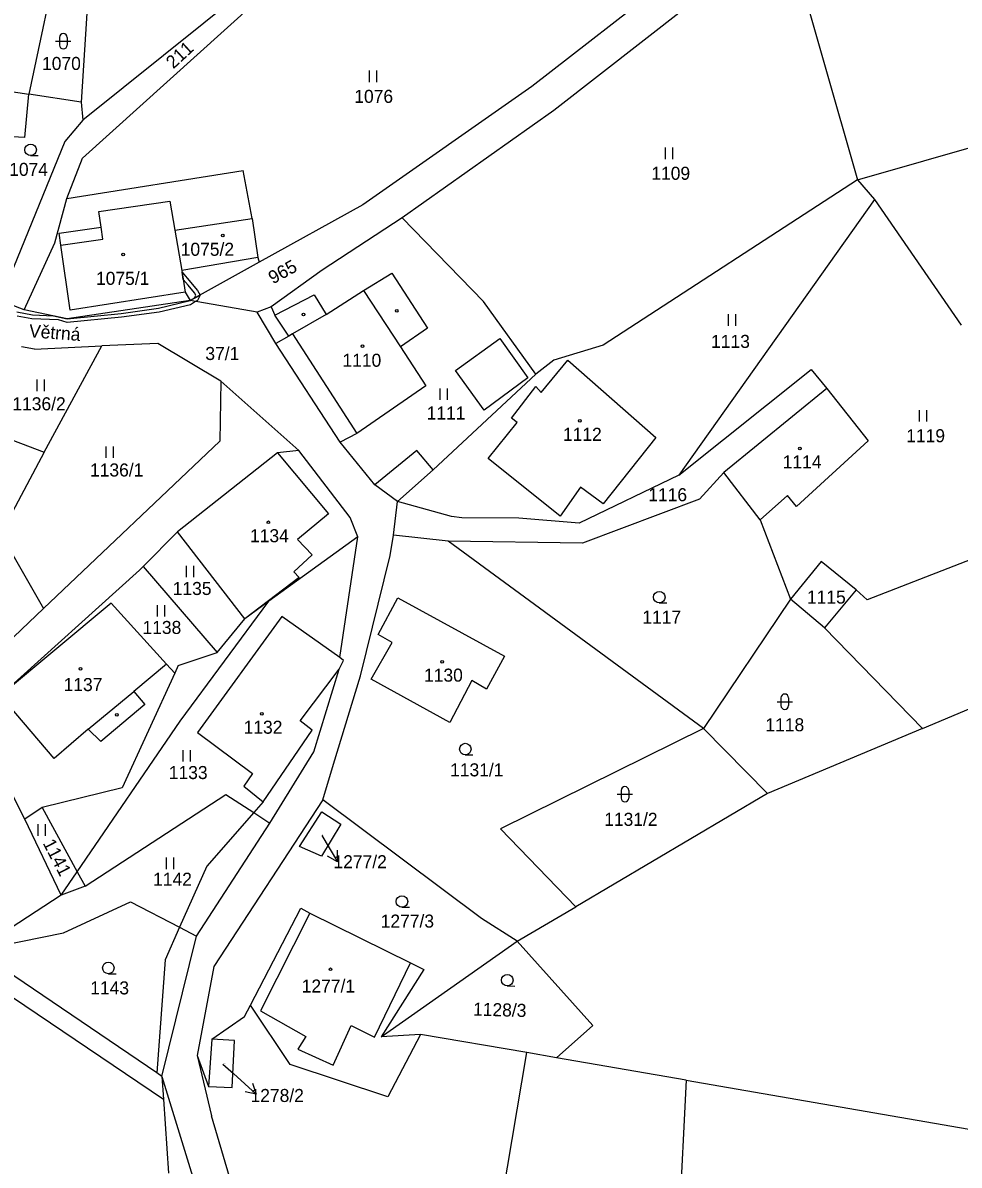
# Model space of a CAD drawing. Extents: x -670359 to -668019, y -978807 to -976674.
# Drawn here: x -670104.9 to -669982.9, y -977860.3 to -977711.4 of the extents above; entities that cross this region are included whole.
import ezdxf

# ---------------------------------------------------------------- set-up
doc = ezdxf.new("R2010")
doc.units = 0
for name, color, linetype in [('Hranice parcel', 7, 'Continuous'), ('Parcelní čísla', 7, 'Continuous'), ('Pop  PČ popisy', 7, 'Continuous'), ('Vnitřní kresba', 7, 'Continuous'), ('Věcná břemena k části', 7, 'Continuous'), ('Značky budov', 7, 'Continuous'), ('Značky kultur', 7, 'Continuous')]:
    doc.layers.add(name, color=color, linetype=linetype)

msp = doc.modelspace()

# ---------------------------------------------------------------- linework, layer by layer
at = {"layer": 'Hranice parcel'}
for p, q in [((-670075.04, -977736.87), (-670076.2, -977730.61)), ((-670085.1, -977738.43), (-670075.04, -977736.87)), ((-670075.04, -977736.87), (-670074.28, -977741.98)), ((-670085.1, -977738.43), (-670084.21, -977743.67)), ((-670084.21, -977743.67), (-670083.75, -977746.5)), ((-670083.75, -977746.5), (-670083.13, -977747.6)), ((-670040.51, -977831.14), (-670030.66, -977842.12)), ((-670030.66, -977842.12), (-670035.36, -977846.32)), ((-670035.36, -977846.32), (-670039.24, -977845.65)), ((-670018.5, -977849.23), (-670035.36, -977846.32))]:
    msp.add_line(p, q, dxfattribs=at)
for points in [[(-670100, -977701.17), (-670104.16, -977720.69)], [(-670096, -977701.2), (-670097.32, -977721.73)], [(-670005.01, -977700.79), (-669996.13, -977731.83)], [(-670097.16, -977729.02), (-670067.28, -977702.04)], [(-670020.57, -977705.64), (-670038.59, -977719.67)], [(-670076.09, -977707.16), (-670097.12, -977724.06)], [(-670018.27, -977709.18), (-670035.74, -977722.81)], [(-670038.59, -977719.67), (-670060.63, -977735.12)], [(-669996.13, -977731.83), (-669953.55, -977719.62)], [(-670109.04, -977719.94), (-670104.16, -977720.69)], [(-670097.32, -977721.73), (-670104.16, -977720.69)], [(-670097.32, -977721.73), (-670097.12, -977724.06)], [(-670097.12, -977724.06), (-670099.46, -977726.85)], [(-670035.74, -977722.81), (-670055.47, -977736.78)], [(-670099.46, -977726.85), (-670106.63, -977744.47)], [(-670099.2, -977734.29), (-670097.16, -977729.02)], [(-670099.2, -977734.29), (-670076.2, -977730.61)], [(-669996.13, -977731.83), (-670029.31, -977753.41)], [(-669996.13, -977731.83), (-669993.93, -977734.4)], [(-670100.76, -977740.04), (-670099.2, -977734.29)], [(-669993.93, -977734.4), (-670019.43, -977770.35)], [(-669993.93, -977734.4), (-669982.65, -977750.8)], [(-670060.63, -977735.12), (-670074.12, -977742.6)], [(-670055.47, -977736.78), (-670065.91, -977743.63)], [(-670044.91, -977747.7), (-670055.47, -977736.78)], [(-670104.74, -977748.8), (-670100.76, -977740.04)], [(-670074.28, -977741.98), (-670074.12, -977742.6)], [(-670074.12, -977742.6), (-670083.13, -977747.6)], [(-670065.91, -977743.63), (-670072.58, -977748.39)], [(-670060.55, -977746.28), (-670056.85, -977744.02)], [(-670056.85, -977744.02), (-670052.18, -977751.17)], [(-670065.38, -977749.4), (-670060.55, -977746.28)], [(-670104.74, -977748.8), (-670109.17, -977747.09)], [(-670083.13, -977747.6), (-670099.15, -977749.96)], [(-670074.4, -977749.12), (-670083.13, -977747.6)], [(-670072.1, -977749.51), (-670066.96, -977746.83)], [(-670066.96, -977746.83), (-670065.38, -977749.4)], [(-670038.06, -977757.19), (-670044.91, -977747.7)], [(-670099.15, -977749.96), (-670104.74, -977748.8)], [(-670072.58, -977748.39), (-670074.4, -977749.12)], [(-670071.96, -977753.19), (-670074.4, -977749.12)], [(-670072.58, -977748.39), (-670072.1, -977749.51)], [(-670052.18, -977751.17), (-670055.72, -977753.63)], [(-670103.42, -977753.93), (-670105.1, -977753.62)], [(-670103.42, -977753.93), (-670094.63, -977753.51)], [(-670102.16, -977767.34), (-670094.63, -977753.51)], [(-670087.33, -977753.17), (-670094.63, -977753.51)], [(-670079.12, -977758.1), (-670087.33, -977753.17)], [(-670063.57, -977766.05), (-670071.96, -977753.19)], [(-670055.72, -977753.63), (-670052.4, -977758.69)], [(-670029.31, -977753.41), (-670035.73, -977755.36)], [(-670035.73, -977755.36), (-670038.06, -977757.19)], [(-670037.36, -977759.59), (-670033.89, -977755.38)], [(-670033.89, -977755.38), (-670022.44, -977765.45)], [(-670019.43, -977770.35), (-670002.21, -977756.56)], [(-670002.21, -977756.56), (-670000.15, -977759.05)], [(-670079.12, -977758.1), (-670079.26, -977765.94)], [(-670068.94, -977767.13), (-670079.12, -977758.1)], [(-670038.06, -977757.19), (-670051.44, -977769.65)], [(-670052.4, -977758.69), (-670061.41, -977764.94)], [(-670041.23, -977762.92), (-670038.05, -977758.8)], [(-670038.05, -977758.8), (-670037.36, -977759.59)], [(-670000.15, -977759.05), (-670013.59, -977770)], [(-670000.15, -977759.05), (-669994.75, -977765.89)], [(-670044.3, -977768.18), (-670040.51, -977763.49)], [(-670040.51, -977763.49), (-670041.23, -977762.92)], [(-670108.36, -977764.99), (-670102.16, -977767.34)], [(-670061.41, -977764.94), (-670063.57, -977766.05)], [(-670022.44, -977765.45), (-670029.3, -977774.1)], [(-669994.75, -977765.89), (-670004.1, -977774.46)], [(-670102.16, -977767.34), (-670107.81, -977777.99)], [(-670079.26, -977765.94), (-670102.21, -977787.73)], [(-670068.94, -977767.13), (-670071.75, -977767.43)], [(-670062.28, -977775.89), (-670068.94, -977767.13)], [(-670059.05, -977771.6), (-670063.57, -977766.05)], [(-670071.75, -977767.43), (-670084.78, -977777.74)], [(-670034.92, -977775.7), (-670044.3, -977768.18)], [(-670051.44, -977769.65), (-670056.11, -977773.78)], [(-670019.43, -977770.35), (-670032.43, -977776.6)], [(-670013.59, -977770), (-670016.73, -977773.49)], [(-670008.83, -977776.19), (-670013.59, -977770)], [(-670056.11, -977773.78), (-670059.05, -977771.6)], [(-670032.25, -977771.9), (-670034.92, -977775.7)], [(-670029.3, -977774.1), (-670032.25, -977771.9)], [(-670005.29, -977773.01), (-670008.83, -977776.19)], [(-670004.1, -977774.46), (-670005.29, -977773.01)], [(-670056.62, -977778.17), (-670056.11, -977773.78)], [(-670049.08, -977775.75), (-670056.11, -977773.78)], [(-670016.73, -977773.49), (-670031.98, -977779.22)], [(-670061.26, -977778.38), (-670062.28, -977775.89)], [(-670047.72, -977775.92), (-670049.08, -977775.75)], [(-670040.28, -977775.97), (-670047.72, -977775.92)], [(-670032.43, -977776.6), (-670040.28, -977775.97)], [(-670008.83, -977776.19), (-670004.9, -977786.53)], [(-669966.28, -977775.47), (-669994.9, -977786.6)], [(-670084.78, -977777.74), (-670089.23, -977782.26)], [(-670076, -977789.08), (-670084.78, -977777.74)], [(-670107.81, -977777.99), (-670102.21, -977787.73)], [(-670061.26, -977778.38), (-670072.85, -977786.78)], [(-670063.62, -977794.12), (-670061.26, -977778.38)], [(-670057.04, -977780.81), (-670056.62, -977778.17)], [(-670049.5, -977778.94), (-670056.62, -977778.17)], [(-670031.98, -977779.22), (-670049.5, -977778.94)], [(-670016.24, -977803.38), (-670049.5, -977778.94)], [(-670089.7, -977782.74), (-670089.23, -977782.26)], [(-670089.23, -977782.26), (-670079.61, -977793.47)], [(-670060.91, -977796.54), (-670057.04, -977780.81)], [(-670000.87, -977781.6), (-670004.9, -977786.53)], [(-669996.33, -977785.31), (-670000.87, -977781.6)], [(-670089.7, -977782.74), (-670107.82, -977799.09)], [(-669987.66, -977803.37), (-669944.4, -977785.17)], [(-670058.63, -977791.12), (-670056.07, -977786.35)], [(-670056.07, -977786.35), (-670042.14, -977793.95)], [(-670004.9, -977786.53), (-670016.24, -977803.38)], [(-670000.45, -977790.24), (-670004.9, -977786.53)], [(-669996.33, -977785.31), (-670000.45, -977790.24)], [(-669994.9, -977786.6), (-669996.33, -977785.31)], [(-670114.79, -977799.68), (-670102.21, -977787.73)], [(-670093.41, -977787.03), (-670107.82, -977799.09)], [(-670086.19, -977795), (-670093.41, -977787.03)], [(-670072.85, -977786.78), (-670076, -977789.08)], [(-670071.18, -977788.79), (-670082.17, -977803.91)], [(-670079.61, -977793.47), (-670076, -977789.08)], [(-670063.62, -977794.12), (-670071.18, -977788.79)], [(-670056.8, -977792.17), (-670058.63, -977791.12)], [(-670000.45, -977790.24), (-669987.66, -977803.37)], [(-670059.55, -977796.95), (-670056.8, -977792.17)], [(-670084.67, -977795.17), (-670079.61, -977793.47)], [(-670063.14, -977794.52), (-670063.62, -977794.12)], [(-670042.14, -977793.95), (-670044.52, -977798.25)], [(-670085.13, -977796.17), (-670086.19, -977795)], [(-670084.67, -977795.17), (-670085.13, -977796.17)], [(-670068.8, -977802.4), (-670063.71, -977795.64)], [(-670066.98, -977806.41), (-670063.71, -977795.64)], [(-670063.71, -977795.64), (-670063.14, -977794.52)], [(-670085.13, -977796.17), (-670091.99, -977811.12)], [(-670064.44, -977808.03), (-670060.91, -977796.54)], [(-670049.27, -977802.62), (-670059.55, -977796.95)], [(-670046.4, -977797.15), (-670049.27, -977802.62)], [(-670044.52, -977798.25), (-670046.4, -977797.15)], [(-670104.66, -977815.19), (-670111.29, -977802.18)], [(-670067.2, -977803.61), (-670068.8, -977802.4)], [(-670082.17, -977803.91), (-670075.01, -977809.24)], [(-670073.59, -977812.93), (-670067.2, -977803.61)], [(-670016.24, -977803.38), (-670042.67, -977816.49)], [(-670007.89, -977811.86), (-670016.24, -977803.38)], [(-669987.66, -977803.37), (-670007.89, -977811.86)], [(-670072.73, -977815.73), (-670066.98, -977806.41)], [(-670065.84, -977812.71), (-670064.44, -977808.03)], [(-670075.01, -977809.24), (-670076.14, -977810.91)], [(-670091.99, -977811.12), (-670102.41, -977813.68)], [(-670096.8, -977823.96), (-670078.47, -977812.01)], [(-670078.47, -977812.01), (-670074.84, -977814.36)], [(-670076.14, -977810.91), (-670073.59, -977812.93)], [(-670007.89, -977811.86), (-670032.86, -977826.62)], [(-670065.84, -977812.71), (-670080.05, -977834.44)], [(-670045.13, -977828.18), (-670065.84, -977812.71)], [(-670102.41, -977813.68), (-670104.66, -977815.19)], [(-670102.41, -977813.68), (-670097.83, -977822.07)], [(-670074.84, -977814.36), (-670072.73, -977815.73)], [(-670068.89, -977818.76), (-670065.96, -977814.27)], [(-670065.96, -977814.27), (-670063.47, -977815.85)], [(-670099.93, -977825.14), (-670104.66, -977815.19)], [(-670082.28, -977830.46), (-670072.73, -977815.73)], [(-670063.47, -977815.85), (-670066, -977820.02)], [(-670042.67, -977816.49), (-670032.86, -977826.62)], [(-670066, -977820.02), (-670068.89, -977818.76)], [(-670097.83, -977822.07), (-670096.8, -977823.96)], [(-670096.8, -977823.96), (-670099.93, -977825.14)], [(-670099.93, -977825.14), (-670111.02, -977832.34)], [(-670099.64, -977830.02), (-670090.89, -977826)], [(-670090.89, -977826), (-670084.5, -977829.31)], [(-670075.27, -977839.47), (-670068.69, -977826.83)], [(-670068.69, -977826.83), (-670067.52, -977827.46)], [(-670040.51, -977831.14), (-670032.86, -977826.62)], [(-670067.52, -977827.46), (-670054.41, -977833.94)], [(-670040.51, -977831.14), (-670045.13, -977828.18)], [(-670084.5, -977829.31), (-670082.28, -977830.46)], [(-670111.02, -977832.34), (-670099.64, -977830.02)], [(-670086.79, -977848.75), (-670082.28, -977830.46)], [(-670058.24, -977843.59), (-670040.51, -977831.14)], [(-670087.45, -977848.3), (-670111.02, -977832.34)], [(-670054.41, -977833.94), (-670052.65, -977834.81)], [(-670111.28, -977835.06), (-670086.58, -977851.74)], [(-670080.05, -977834.44), (-670082.19, -977846.01)], [(-670052.65, -977834.81), (-670058.24, -977843.59)], [(-670076.05, -977840.94), (-670075.27, -977839.47)], [(-670070.1, -977847.22), (-670075.27, -977839.47)], [(-670080.28, -977843.89), (-670076.05, -977840.94)], [(-670053.08, -977843.28), (-670058.24, -977843.59)], [(-670053.08, -977843.28), (-670057.36, -977851.43)], [(-670039.24, -977845.65), (-670053.08, -977843.28)], [(-670080.28, -977843.89), (-670080.71, -977850.05)], [(-670077.33, -977844.09), (-670080.28, -977843.89)], [(-670077.66, -977850.21), (-670077.33, -977844.09)], [(-670082.19, -977846.01), (-670080.34, -977853.91)], [(-670082.19, -977846.01), (-670080.71, -977850.05)], [(-670042.41, -977864.47), (-670039.24, -977845.65)], [(-670057.36, -977851.43), (-670070.1, -977847.22)], [(-670086.79, -977848.75), (-670087.45, -977848.3)], [(-670086.79, -977848.75), (-670082.65, -977862.31)], [(-670086.79, -977848.75), (-670086.58, -977851.74)], [(-670018.5, -977849.23), (-670020.31, -977885.6)], [(-670018.5, -977849.23), (-669960.55, -977859.27)], [(-670080.71, -977850.05), (-670077.66, -977850.21)], [(-670086.58, -977851.74), (-670085.93, -977861.38)], [(-670078.01, -977861.85), (-670080.34, -977853.91)]]:
    msp.add_lwpolyline(points, dxfattribs=at)
at = {"layer": 'Parcelní čísla'}
for p, q in [((-670063.94, -977819.27), (-670063.92, -977820.77)), ((-670078.86, -977847.17), (-670077.49, -977848.39)), ((-670074.98, -977849.63), (-670074.51, -977851.05))]:
    msp.add_line(p, q, dxfattribs=at)
for points in [[(-670065.96, -977817.33), (-670063.92, -977820.77), (-670065.23, -977820.04)], [(-670077.49, -977848.39), (-670074.51, -977851.05), (-670075.97, -977850.75)]]:
    msp.add_lwpolyline(points, dxfattribs=at)
at = {"layer": 'Vnitřní kresba'}
for p, q in [((-670095.03, -977735.97), (-670085.75, -977734.63)), ((-670094.73, -977738.03), (-670095.03, -977735.97)), ((-670085.75, -977734.63), (-670085.1, -977738.43)), ((-670100.2, -977738.82), (-670094.73, -977738.03)), ((-670099.97, -977740.38), (-670100.2, -977738.82)), ((-670094.51, -977739.59), (-670094.73, -977738.03)), ((-670099.97, -977740.38), (-670094.51, -977739.59)), ((-670098.75, -977748.84), (-670099.97, -977740.38)), ((-670074.28, -977741.98), (-670084.21, -977743.67)), ((-670083.75, -977746.5), (-670098.75, -977748.84))]:
    msp.add_line(p, q, dxfattribs=at)
for points in [[(-670104.66, -977726.33), (-670104.16, -977720.69)], [(-670104.66, -977726.33), (-670109.7, -977726.06)], [(-670060.55, -977746.28), (-670055.72, -977753.63)], [(-670065.38, -977749.4), (-670069.79, -977751.93)], [(-670070.28, -977752.24), (-670072.1, -977749.51)], [(-670070.28, -977752.24), (-670071.96, -977753.19)], [(-670069.79, -977751.93), (-670070.28, -977752.24)], [(-670069.79, -977751.93), (-670061.41, -977764.94)], [(-670048.54, -977756.72), (-670042.75, -977752.52)], [(-670042.75, -977752.52), (-670039.11, -977757.66)], [(-670044.82, -977761.86), (-670048.54, -977756.72)], [(-670039.11, -977757.66), (-670044.82, -977761.86)], [(-670053.58, -977767.16), (-670059.05, -977771.6)], [(-670051.44, -977769.65), (-670053.58, -977767.16)], [(-670071.75, -977767.43), (-670065.08, -977775.39)], [(-670065.08, -977775.39), (-670069.11, -977778.73)], [(-670069.11, -977778.73), (-670067.2, -977780.74)], [(-670067.2, -977780.74), (-670069.62, -977782.96)], [(-670068.9, -977783.69), (-670076, -977789.08)], [(-670069.62, -977782.96), (-670068.9, -977783.69)], [(-670084.4, -977802.45), (-670072.85, -977786.78)], [(-670086.19, -977795), (-670090.46, -977798.57)], [(-670096.41, -977803.49), (-670090.46, -977798.57)], [(-670090.46, -977798.57), (-670089.03, -977800.26)], [(-670100.84, -977807.3), (-670107.82, -977799.09)], [(-670089.03, -977800.26), (-670094.74, -977805.1)], [(-670097.83, -977822.07), (-670084.4, -977802.45)], [(-670096.41, -977803.49), (-670100.84, -977807.3)], [(-670094.74, -977805.1), (-670096.41, -977803.49)], [(-670073.59, -977812.93), (-670074.84, -977814.36)], [(-670074.84, -977814.36), (-670080.94, -977821.35)], [(-670099.93, -977825.14), (-670097.83, -977822.07)], [(-670080.94, -977821.35), (-670084.5, -977829.31)], [(-670067.52, -977827.46), (-670073.97, -977840.21)], [(-670084.5, -977829.31), (-670086.39, -977833.55)], [(-670086.39, -977833.55), (-670087.45, -977848.3)], [(-670059.08, -977843.63), (-670054.41, -977833.94)], [(-670073.97, -977840.21), (-670068.04, -977843.53)], [(-670064.5, -977847.3), (-670062.13, -977842.13)], [(-670062.13, -977842.13), (-670059.08, -977843.63)], [(-670068.04, -977843.53), (-670069.07, -977845.21)], [(-670069.07, -977845.21), (-670064.5, -977847.3)]]:
    msp.add_lwpolyline(points, dxfattribs=at)
at = {"layer": 'Věcná břemena k části'}
for p, q in [((-670087.24, -977748.6), (-670083.13, -977747.6)), ((-670082.41, -977747.73), (-670083.07, -977748.14)), ((-670082.14, -977747.56), (-670082.41, -977747.73)), ((-670081.83, -977746.88), (-670082.14, -977747.56)), ((-670105.71, -977749.07), (-670103.67, -977749.47)), ((-670103.67, -977749.47), (-670100.94, -977749.59)), ((-670099.15, -977749.96), (-670092.13, -977749.26)), ((-670092.13, -977749.26), (-670087.24, -977748.6)), ((-670087.14, -977749.1), (-670092.07, -977749.76)), ((-670083.07, -977748.14), (-670087.14, -977749.1)), ((-670103.73, -977749.97), (-670105.67, -977749.61)), ((-670100.29, -977750.12), (-670103.73, -977749.97)), ((-670100.94, -977749.59), (-670099.15, -977749.96)), ((-670099.15, -977750.43), (-670100.29, -977750.12)), ((-670092.07, -977749.76), (-670099.15, -977750.43))]:
    msp.add_line(p, q, dxfattribs=at)
for points in [[(-670084.17, -977743.9), (-670083.52, -977744.67)], [(-670083.39, -977745.59), (-670084.02, -977744.84), (-670084.17, -977743.9)], [(-670083.52, -977744.67), (-670082.15, -977746.29), (-670081.83, -977746.88), (-670083.13, -977747.6), (-670082.54, -977747.22), (-670082.39, -977746.89), (-670082.57, -977746.57), (-670083.39, -977745.59)], [(-670083.13, -977747.6), (-670081.83, -977746.88)]]:
    msp.add_lwpolyline(points, dxfattribs=at)
at = {"layer": 'Značky budov'}
for centre in [(-670078.88, -977739.11), (-670091.85, -977741.58), (-670060.65, -977753.54), (-670032.33, -977763.28), (-670003.65, -977766.87), (-670072.93, -977776.5), (-670097.41, -977795.62), (-670050.28, -977794.68), (-670073.79, -977801.47), (-670064.82, -977834.79)]:
    msp.add_circle(centre, 0.175, dxfattribs=at)
at = {"layer": 'Značky kultur'}
for p, q in [((-670100.15, -977713.27), (-670100.15, -977714.27)), ((-670099.15, -977713.27), (-670099.15, -977714.27)), ((-670100.65, -977713.77), (-670098.65, -977713.77)), ((-670059.77, -977717.61), (-670059.77, -977719.11)), ((-670058.77, -977719.11), (-670058.77, -977717.61)), ((-670021.2, -977727.64), (-670021.2, -977729.14)), ((-670020.2, -977729.14), (-670020.2, -977727.64)), ((-670103.91, -977728.68), (-670102.91, -977728.68)), ((-670013, -977749.38), (-670013, -977750.88)), ((-670012, -977750.88), (-670012, -977749.38)), ((-670103.1, -977757.89), (-670103.1, -977759.39)), ((-670102.1, -977759.39), (-670102.1, -977757.89)), ((-670050.58, -977759.05), (-670050.58, -977760.55)), ((-670049.58, -977760.55), (-670049.58, -977759.05)), ((-669988.12, -977761.86), (-669988.12, -977763.36)), ((-669987.12, -977763.36), (-669987.12, -977761.86)), ((-670094.09, -977766.6), (-670094.09, -977768.1)), ((-670093.09, -977768.1), (-670093.09, -977766.6)), ((-670083.63, -977782.17), (-670083.63, -977783.67)), ((-670082.63, -977783.67), (-670082.63, -977782.17)), ((-670087.41, -977787.29), (-670087.41, -977788.79)), ((-670086.41, -977788.79), (-670086.41, -977787.29)), ((-670021.98, -977787.01), (-670020.98, -977787.01)), ((-670006.63, -977799.89), (-670004.63, -977799.89)), ((-670006.13, -977799.39), (-670006.13, -977800.39)), ((-670005.13, -977799.39), (-670005.13, -977800.39)), ((-670084.09, -977806.2), (-670084.09, -977807.7)), ((-670083.09, -977807.7), (-670083.09, -977806.2)), ((-670047.26, -977806.82), (-670046.26, -977806.82)), ((-670027.46, -977811.96), (-670025.46, -977811.96)), ((-670026.96, -977811.46), (-670026.96, -977812.46)), ((-670025.96, -977811.46), (-670025.96, -977812.46)), ((-670102.95, -977815.87), (-670102.95, -977817.37)), ((-670101.95, -977817.37), (-670101.95, -977815.87)), ((-670086.24, -977820.21), (-670086.24, -977821.71)), ((-670085.24, -977821.71), (-670085.24, -977820.21)), ((-670055.52, -977826.69), (-670054.52, -977826.69)), ((-670093.78, -977835.36), (-670092.78, -977835.36)), ((-670041.81, -977836.95), (-670040.81, -977836.98))]:
    msp.add_line(p, q, dxfattribs=at)
for centre, radius in [((-670103.91, -977727.93), 0.75), ((-670078.88, -977739.11), 0.175), ((-670091.85, -977741.58), 0.175), ((-670068.35, -977749.39), 0.175), ((-670056.2, -977748.92), 0.175), ((-670060.65, -977753.54), 0.175), ((-670032.33, -977763.28), 0.175), ((-670003.65, -977766.87), 0.175), ((-670072.93, -977776.5), 0.175), ((-670021.98, -977786.26), 0.75), ((-670097.41, -977795.62), 0.175), ((-670050.28, -977794.68), 0.175), ((-670092.66, -977801.61), 0.175), ((-670073.79, -977801.47), 0.175), ((-670047.26, -977806.07), 0.75), ((-670055.52, -977825.94), 0.75), ((-670093.78, -977834.61), 0.75), ((-670064.82, -977834.79), 0.175), ((-670041.79, -977836.2), 0.75)]:
    msp.add_circle(centre, radius, dxfattribs=at)
for centre, start, end in [((-670099.65, -977713.27), 0, 180), ((-670099.65, -977714.27), 180, 0), ((-670005.63, -977799.39), 0, 180), ((-670005.63, -977800.39), 180, 0), ((-670026.46, -977811.46), 0, 180), ((-670026.46, -977812.46), 180, 0)]:
    msp.add_arc(centre, 0.5, start, end, dxfattribs=at)

# ---------------------------------------------------------------- texts
at = {"layer": 'Parcelní čísla'}
for s, rotation, p in [('211', 42.6863, (-670085.31, -977717.45)), ('965', 28.8725, (-670072.33, -977745.49)), ('1141', 297.4928, (-670102.37, -977818.33)), ('1128/3', 358.4411, (-670046.27, -977840.82))]:
    msp.add_text(s, height=1.7, rotation=rotation, dxfattribs=at).set_placement(p)
for s, height, p in [('1070', 1.7, (-670102.42, -977717.52)), ('1076', 1.7, (-670061.73, -977721.81)), ('1074', 1.7, (-670106.7, -977731.33)), ('1109', 1.7, (-670023.02, -977731.84)), ('1075/2', 1.7, (-670084.35, -977741.75)), ('1075/1', 1.7, (-670095.39, -977745.54)), ('1113', 1.7, (-670015.23, -977753.76)), ('37/1', 1.7, (-670081.14, -977755.34)), ('1110', 1.7, (-670063.27, -977756.22)), ('1136/2', 1.7, (-670106.29, -977761.9)), ('1111', 1.7, (-670052.3, -977763.1)), ('1112', 1.7, (-670034.54, -977765.88)), ('1119', 1.7, (-669989.8, -977766.06)), ('1136/1', 1.7, (-670096.17, -977770.53)), ('1114', 1.7, (-670005.9, -977769.47)), ('1116', 1.7, (-670023.42, -977773.75)), ('1134', 1.7, (-670075.32, -977779.1)), ('1135', 1.7, (-670085.39, -977785.98)), ('1115', 1.7, (-670002.74, -977787.1)), ('1117', 1.7, (-670024.19, -977789.71)), ('1138', 1.7, (-670089.33, -977791.06)), ('1130', 1.7, (-670052.64, -977797.28)), ('1137', 1.7, (-670099.61, -977798.51)), ('1132', 1.7, (-670076.15, -977804.07)), ('1118', 1.7, (-670008.15, -977803.75)), ('1133', 1.7, (-670085.9, -977809.98)), ('1131/1', 1.7, (-670049.24, -977809.63)), ('1131/2', 1.7, (-670029.16, -977816.08)), ('1277/2', 0.1, (-670065.96, -977817.33)), ('1277/2', 1.7, (-670064.44, -977821.61)), ('1142', 1.7, (-670087.95, -977823.89)), ('1277/3', 1.7, (-670058.29, -977829.35)), ('1143', 1.7, (-670096.14, -977838.06)), ('1277/1', 1.7, (-670068.58, -977837.82)), ('1278/2', 0.1, (-670078.86, -977847.17)), ('1278/2', 1.7, (-670075.25, -977852.09))]:
    msp.add_text(s, height=height, dxfattribs=at).set_placement(p)
at = {"layer": 'Pop  PČ popisy'}
msp.add_text('Větrná', height=1.7, rotation=355.702, dxfattribs=at).set_placement((-670104.16, -977752.36))

doc.saveas('drawing.dxf')
